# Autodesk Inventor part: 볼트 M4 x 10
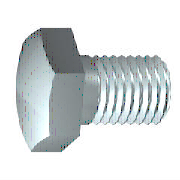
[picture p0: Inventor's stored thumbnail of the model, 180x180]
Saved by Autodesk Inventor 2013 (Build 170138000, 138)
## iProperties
Created: 2012-02
Part Number: 볼트 M4 x 10
Material: 스테인리스강
Description: 6각 머리 나사
Document SubType Name: Modeling
Standard: ISO 4017
Designer: mduedu
Standard Revision: Third edition 1999-08-15
Standards Organization: ISO
Language: ko-KR
Size Designation: M4 x 10
Categories: <MemberInstance><Categories><Category DisplayName="조임쇠" InternalName="e4da775c-781d-43d5-af7c-5136215cf5a6" Mnemonic="FSTN"><Category DisplayName="볼트" InternalN
Density: 8.08 g/cm^3
IsCustomPart: 0
Author: mduedu
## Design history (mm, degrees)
sketch "스케치1"
  geometry: L1 (0, 3.015)-(0, 2); L2 (1.25, 2)-(10, 2); L3 (10, 2)-(10, 0); L4 (10, 0)-(-0.4, 0); L5 (-2.48, 0)-(12.08, 0) reference; L6 (-0.4, 0)-(-0.4, 3.015); L7 (-0.4, 3.015)-(0, 3.015); L8 (1.25, 2)-(0.82, 2); L9 (0.82, 2)-(0, 2); L10 (0, -0.603)-(0, 3.618) reference
  constraints: 16 end point, 2 collinear, 2 perpendicular, 1 parallel
  dimensions: "d0" = 10 distance between parallel lines of L3 L1 (= NLG); "d1" = 8.75 distance from line of L2.start L3 (= GEL); "d2" = 4 diameter of L2 L4 (= GD); "d9" = 0.4001 distance between parallel lines of L6 L1 (computed from SD); "d10" = 6.03 diameter of L7 L4 (= SD2); "d13" = 0.42952 distance of L2.start L8.end (computed from GAL); "d14" = 4 diameter of L9 L4 (= BDM)
revolve "본체" sketch "스케치1" stored, may be unused: angle "d12" = 90 deg
sketch "스케치2"
  geometry: L1 (0, 4.041)-(3.5, 2.021); L2 (3.5, 2.021)-(3.5, -2.021); L3 (3.5, -2.021)-(0, -4.041); L4 (0, -4.041)-(-3.5, -2.021); L5 (-3.5, -2.021)-(-3.5, 2.021); L6 (-3.5, 2.021)-(0, 4.041); 2 further points
  constraints: 12 end point, 1 coincident, 1 vertical, 11 other
  dimensions: "d11" = 7 distance between parallel lines of L5 L2 (= SW)
extrude "머리" join sketch "스케치2" distance "d3" = 2.4 (= KOH - SD); taper "d4" = 0 deg
sketch "스케치4"
  geometry: L1 (-2.8, 3.5)-(-2.8, 4.041); L2 (-2.8, 4.041)-(-2.487, 4.041); L3 (-2.487, 4.041)-(-2.8, 3.5); L4 (-3.28, 0)-(0.08, 0) reference; L5 (-0.4, 4.041)-(-2.8, 4.041) reference; L6 (-2.8, 2.021)-(-2.8, 4.041) reference
  constraints: 6 end point, 2 collinear, 1 perpendicular, 1 vertical
  dimensions: "d5" = 30 deg angle of L3 L1 (= ANG1); "d19" = 7 diameter of L1.start L4 (= SW0)
revolve "모따기1" sketch "스케치4" stored, may be unused: angle "d21" = 90 deg
workplane "Work Plane1"
body "Solid1"
feature "스레드" dims "d15" = 8.75 (= GEL), "d16" = 0
chamfer "모따기2" distance "d6" = 0.42941 (= -0.5 x SPD + 0.5 x GD); stored, may be unused: second distance "d7" = 0.42952 (computed from GUL), angle "d55" = 45 deg
other parameters: "NLG" = 10 [user parameter; used in 1 equation term], "GD" = 4 (= NND) [user parameter; used in 2 equation terms], "BDM" = 4 (= NND) [user parameter; used in 1 equation term], "KOH" = 2.8 [user parameter; used in 1 equation term], "GEL" = 8.75 [user parameter; used in 2 equation terms], "SW" = 7 [user parameter; used in 2 equation terms], "SW0" = 7 (= SW) [user parameter; used in 1 equation term], "SPD" = 3.14117 (= NND - 1.2269 x PTC) [user parameter; used in 1 equation term], "SD2" = 6.03 [user parameter; used in 2 equation terms], "SD" = 0.4 [user parameter; used in 2 equation terms], "ANG1" = 30 deg [user parameter; used in 1 equation term], "GAL" = 0.42941 (= 0.61345 x PTC) [user parameter; used in 1 equation term], "GUL" = 0.42941 (= 0.61345 x PTC) [user parameter; used in 1 equation term], "d8" = 0, "RR" = 0.2 [user parameter], "d57" = 0, "d58" = 0, "TPU" = 14.28571 (computed from PTC) [user parameter], "GD1" = 3.14117 (= THREADDIA - 1.2269 x PTC) [user parameter], "THREADDIA" = 4 [user parameter; used in 1 equation term], "SDH" = 6.03 (= SD2) [user parameter], "SDHG" = 2.1 [user parameter], "TOA" = 30 deg [user parameter], "PTC" = 0.7 [user parameter; used in 5 equation terms], "NND" = 4 [user parameter; used in 3 equation terms], "E0" = 8.085 [user parameter]
